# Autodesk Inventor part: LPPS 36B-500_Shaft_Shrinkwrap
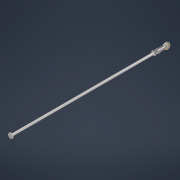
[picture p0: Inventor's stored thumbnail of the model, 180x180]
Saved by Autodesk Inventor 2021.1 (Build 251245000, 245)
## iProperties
Created: 2020-09
Part Number: LPPS 36B-500_Shaft_Shrinkwrap
Material: Generic
Document SubType Name: Modeling
Designer: J. Nielson
Density: 1 g/cm^3
Appearance: Default
Author: J. Nielson
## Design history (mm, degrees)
derived "LPPS 36B-500.iam"
body "Solid1"
node "LPPS-36B-500 ROD.ipt:1"
node "Custom Flanged Nut.ipt:1"
body "Solid2"
node "FEMALE Rod End SW.ipt:1"
body "Solid3"
node "JIS B 1181 - M8x1(4).ipt:1"
body "Solid4"
